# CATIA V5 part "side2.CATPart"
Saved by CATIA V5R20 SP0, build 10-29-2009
Part number: side2
Bounding box of the stored display mesh (mm): x 0 to 18, y -537.349 to 0, z -254.537 to 254.537
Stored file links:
  C:\Users\Dell\Desktop\Documentations\week8 doc\side2.CATPart
  C:\Users\Dell\Desktop\Documentations\week8 doc\Part2.CATPart
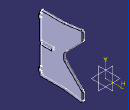
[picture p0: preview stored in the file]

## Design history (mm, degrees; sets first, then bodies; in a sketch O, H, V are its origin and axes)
Body1 (main body)
  Sketch1 on yz-plane, origin (0, 0, 0), H (0, 1, 0), V (0, 0, 1)
    construction line L1 through (0, 0) direction (1, 0)
    point P1 (70.8142, 0)
    construction line L2 through (0, 0) direction (0, 1)
    point P2 (0, 332.8427)
    point P3 (0, 0)
    point P4 (0, 0)
    point P5 (70.8142, 0)
    point P6 (76.4276, -5.6156)
    point P7 (76.4276, 5.6156)
    construction line L3 (0.0005, 472.2536) -> (0.0005, -439.1494)
    point P10 (-177.3491, 176.776)
    point P11 (-332.8423, 0)
    point P12 (-427.4144, -3)
    point P13 (-474.2497, -176.7765)
    point P14 (-474.2497, 176.7765)
    point P15 (-177.3491, -176.776)
    point P17 (-318.7698, 35.3553)
    point P19 (-326.7765, 234.504)
    point P20 (-673.0932, -332.8427)
    point P21 (-673.0932, 332.8427)
    point P22 (-526.7765, 234.504)
    point P23 (-332.8423, 0)
    point P34 (-427.4144, -3)
    line L4 (-177.3491, 185.0603) -> (-177.3491, 244.6408)
    line L5 (-183.207, 170.9181) -> (-318.7698, 35.3553)
    line L6 (-326.7765, 234.504) -> (-516.7765, 234.504)
    line L7 (-526.7765, 224.504) -> (-526.7765, 202.3974)
    line L8 (-526.7765, 202.3974) -> (-536.7765, 202.3974)
    line L9 (-536.7765, 202.3974) -> (-536.7765, 172.3974)
    line L10 (-536.7765, 172.3974) -> (-527.4144, 172.3974)
    line L11 (-527.4144, 172.3974) -> (-527.4144, 9)
    line L12 (-427.4144, 9) -> (-427.4144, -3)
    line L13 (-177.3491, -185.0603) -> (-177.3491, -244.6408)
    line L14 (-183.207, -170.9181) -> (-318.7703, -35.3548)
    line L15 (-188.7858, -254.5371) -> (-327.3491, -234.504)
    line L16 (-188.7858, 254.5371) -> (-326.7765, 234.504)
    line L17 (-327.3491, -234.504) -> (-516.7765, -234.504)
    line L18 (-526.7765, -224.504) -> (-527.3491, -207.6026)
    line L19 (-527.3491, -207.6026) -> (-537.3491, -207.6026)
    line L20 (-537.3491, -207.6026) -> (-537.3491, -177.6026)
    line L21 (-537.3491, -177.6026) -> (-527.3491, -177.6026)
    line L22 (-527.3491, -177.6026) -> (-527.3491, -9)
    line L23 (-427.3491, -9) -> (-427.4144, -3)
    arc A1 centre (-283.4144, 0) radius 50 from (-318.7698, 35.3553) to (-318.7703, -35.3548) ccw
    point P35 (-283.4144, 0)
    line L24 (-427.4144, 9) -> (-527.4144, 9)
    line L25 (-427.3491, -9) -> (-527.3491, -9)
    point P38 (-318.7698, 35.3553)
    arc A2 centre (-516.7765, 224.504) radius 10 from (-516.7765, 234.504) to (-526.7765, 224.504) ccw
    point P39 (-516.7765, 234.504)
    point P40 (-526.7765, 224.504)
    arc A3 centre (-187.3491, 244.6408) radius 10 from (-188.7858, 254.5371) to (-177.3491, 244.6408) cw
    point P42 (-188.7858, 254.5371)
    point P43 (-177.3491, 244.6408)
    arc A4 centre (-197.3491, 185.0603) radius 20 from (-177.3491, 185.0603) to (-183.207, 170.9181) cw
    point P45 (-177.3491, 185.0603)
    point P46 (-183.207, 170.9181)
    point P48 (-526.7765, -224.504)
    point P49 (-516.7765, -234.504)
    arc A5 centre (-516.7765, -224.504) radius 10 from (-516.7765, -234.504) to (-526.7765, -224.504) cw
    point P51 (-177.3491, -244.6408)
    point P52 (-188.7858, -254.5371)
    arc A6 centre (-187.3491, -244.6408) radius 10 from (-188.7858, -254.5371) to (-177.3491, -244.6408) ccw
    point P54 (-183.207, -170.9181)
    point P55 (-177.3491, -185.0603)
    arc A7 centre (-197.3491, -185.0603) radius 20 from (-177.3491, -185.0603) to (-183.207, -170.9181) ccw
    axis line L26 (-333.4144, 34.5415) -> (-333.4144, -88.5483)
    distance L25 L24 = 18
    length L24 = 100
    length L25 = 100
    distance L22 L13 = 350
    distance L10 L21 = 350
    length L9 = 30
    length L20 = 30
    length L8 = 10
    distance P19 P22 = 200
    radius A2 = 10
    radius A3 = 10
    distance A1 L3 = 333.4149
    distance P10 L1 = 176.776
    distance L1 P15 = 176.776
    radius A1 = 50
    radius A4 = 20
    length L21 = 10
    length L19 = 10
    distance L24 L1 = 9
    distance L26 P12 = 94
    vertical: L3 L2
    tangency: A1 L5, A2 L6, A2 L7, A3 L16, A3 L4, A4 L4, A4 L5, L26 A1
    horizontal: L24 H, L25 H
    coincidence: P12 P34, P17 P38, L6 P22, L7 P22, P35 L1, L1 H, L4 P10, L5 P10
    parallelism: L8 L10, L10 L21, L21 L19, L6 L17, L26 L22, L22 L12
    symmetry: P40 P48 L1, P39 P49 L1, A2 A5 L1, P43 P51 L1, P42 P52 L1, A3 A6 L1, P46 P54 L1, P45 P55 L1, A4 A7 L1
  Pad1: profile Sketch1, direction (1, 0, 0), length 18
